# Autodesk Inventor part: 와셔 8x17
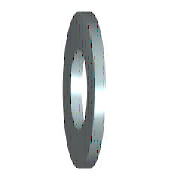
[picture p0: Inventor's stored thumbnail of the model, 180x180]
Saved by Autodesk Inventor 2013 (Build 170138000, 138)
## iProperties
Created: 2012-02
Part Number: 와셔 8x17
Material: 강철, 연강
Description: 평면 와셔
Document SubType Name: Modeling
Standard: KS B 1326
Designer: mduedu
Standards Organization: KS
Language: ko-KR
Size Designation: 8x17
Categories: <MemberInstance><Categories><Category DisplayName="조임쇠" InternalName="e4da775c-781d-43d5-af7c-5136215cf5a6" Mnemonic="FSTN"><Category DisplayName="와셔" InternalN
Density: 7.86 g/cm^3
Mass: 2.05445 g
Surface Area: 4.57416 cm^2
Volume: 0.261381 cm^3
IsCustomPart: 1
Author: mduedu
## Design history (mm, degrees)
sketch "스케치"
  geometry: C1 r 8.5 at (0, 0); C2 r 4.5 at (0, 0); 1 further point
  constraints: 2 centre point, 2 coincident
  dimensions: "d0" = 9 diameter of C2 (= SD1); "d1" = 17 diameter of C1 (= SD2)
extrude "본체" new body sketch "스케치" distance "d2" = 1.6 (= SD); taper "d3" = 0 deg
workaxis "Work Axis1"
workplane "Work Plane1"
body "Solid1"
other parameters: "SD1" = 9 [user parameter; used in 1 equation term], "SD2" = 17 [user parameter; used in 1 equation term], "SD" = 1.6 [user parameter; used in 1 equation term], "d4" = 0, "d5" = 0, "d6" = 0, "d7" = 0, "NND" = 8 [user parameter]
